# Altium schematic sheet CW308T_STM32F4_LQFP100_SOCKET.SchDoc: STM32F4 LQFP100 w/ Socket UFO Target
size Tabloid; DrawnBy: Joe Grand; Organization: Grand Idea Studio, Inc.; Revision: A; SheetNumber: 1; SheetTotal: 1; SheetApproved: YES
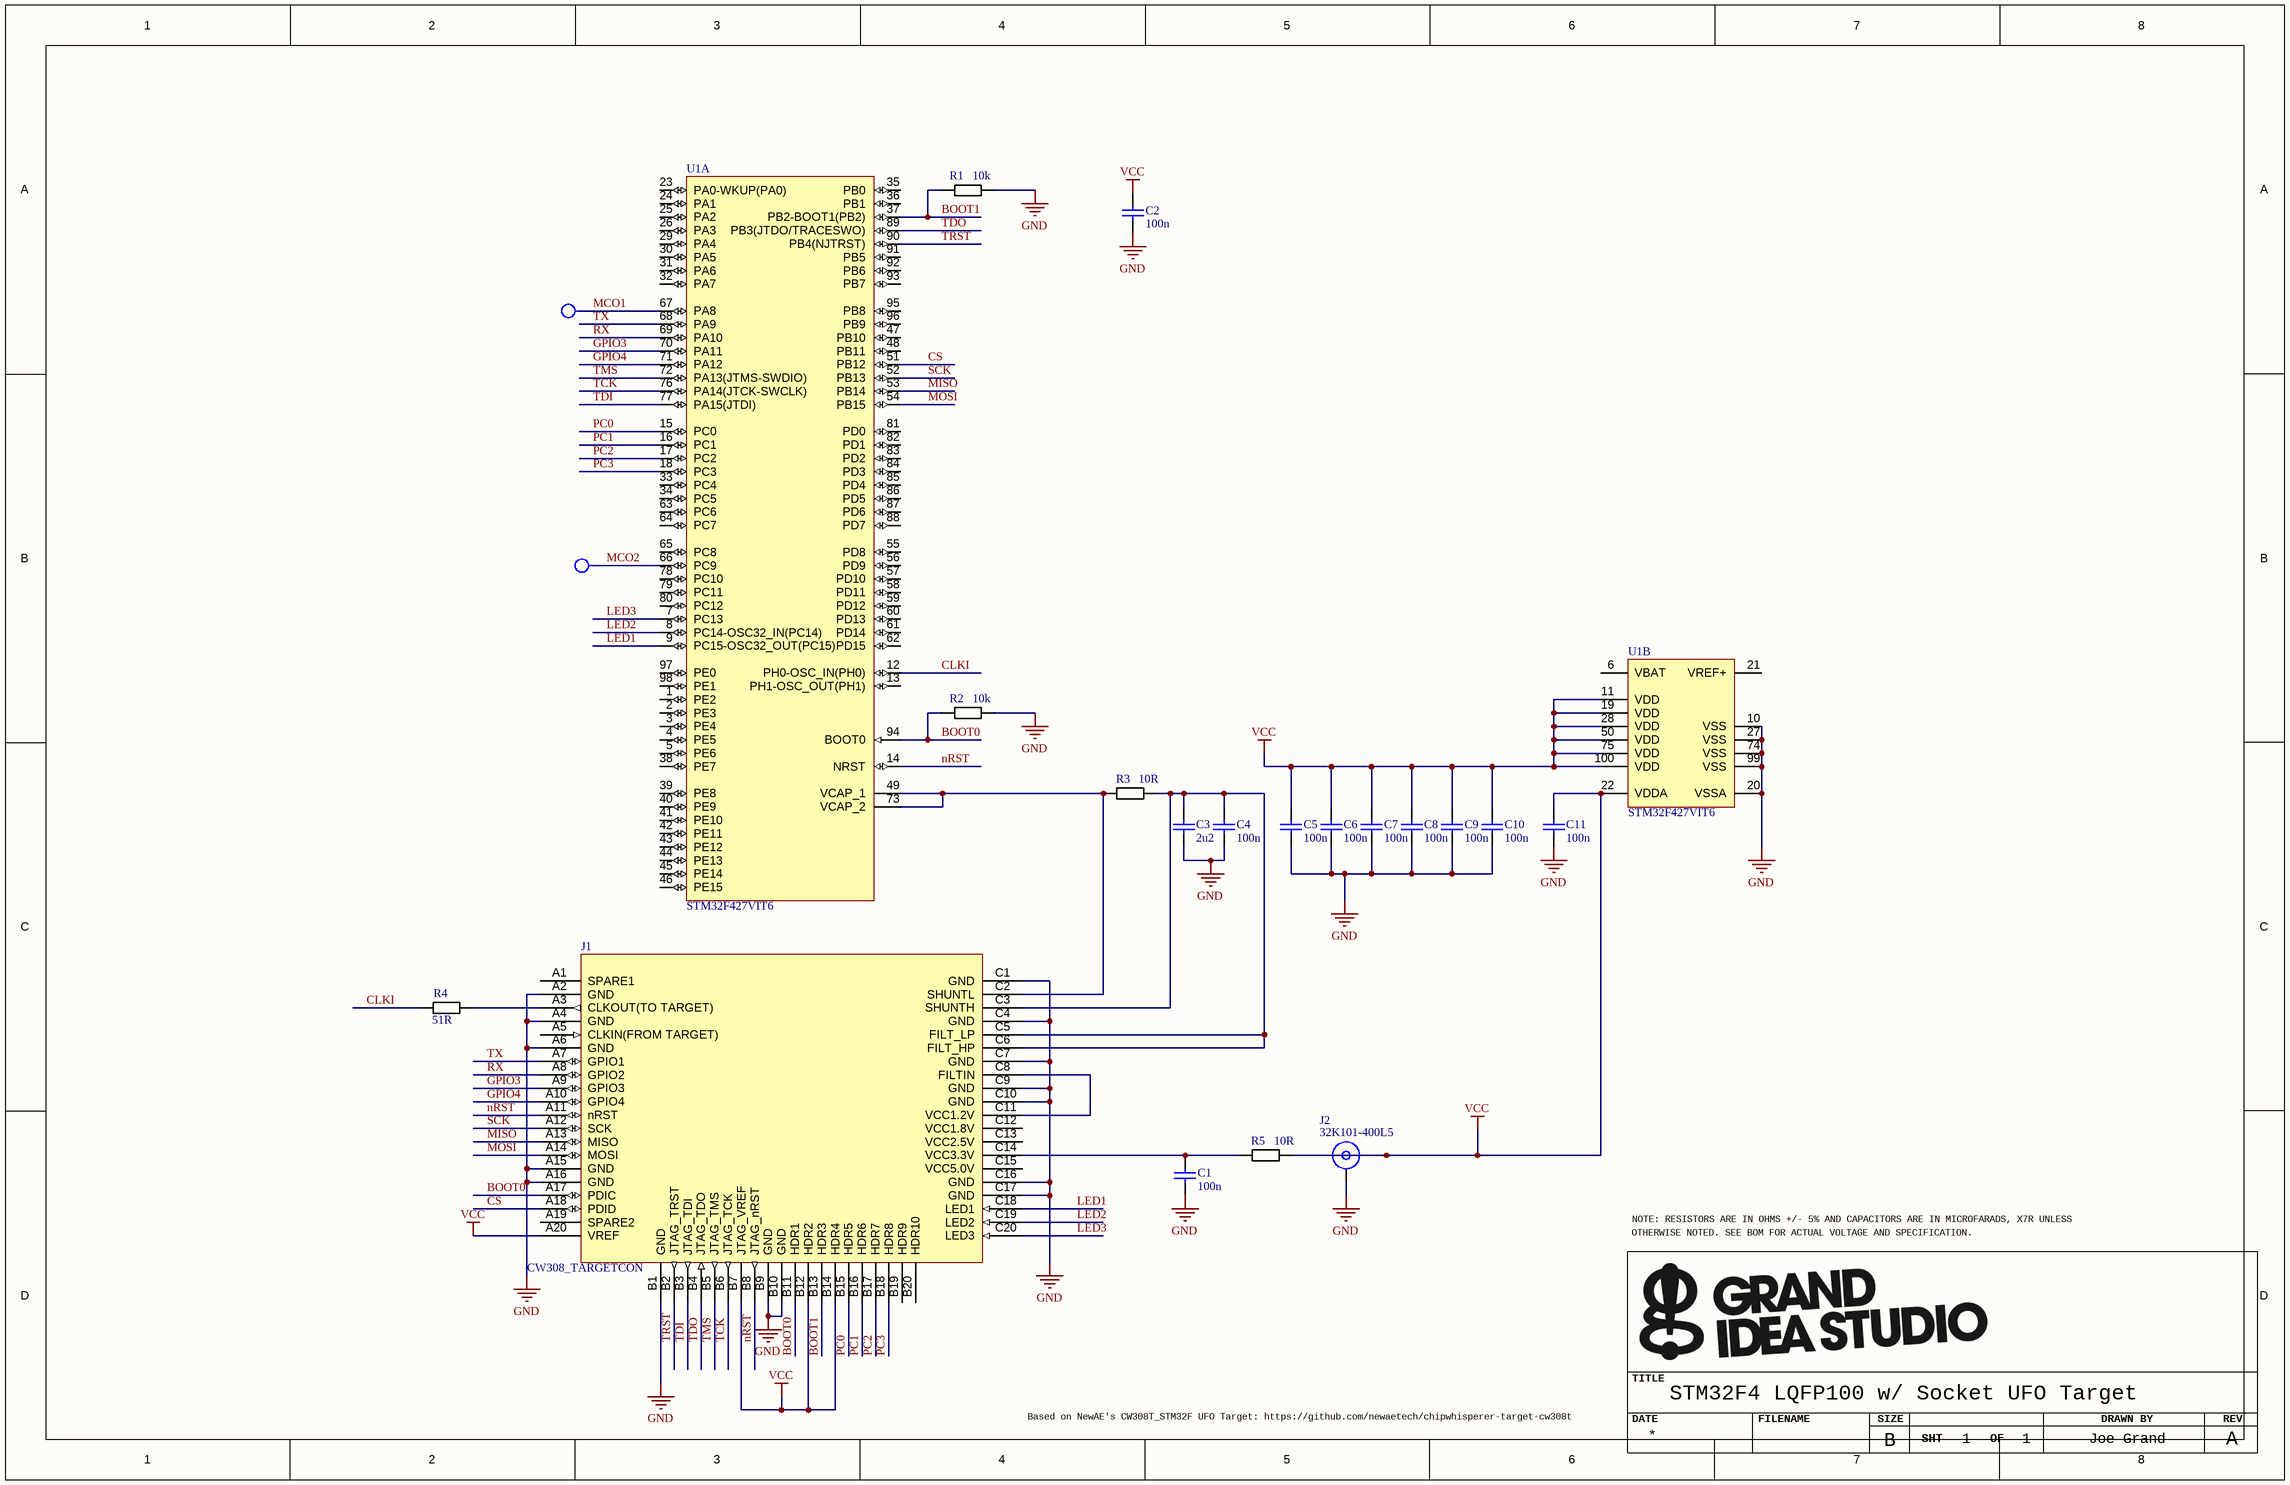
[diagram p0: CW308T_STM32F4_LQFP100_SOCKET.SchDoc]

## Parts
*  Page Size: B  RevCode: A  Page Count: 1  OrgName: Joe Grand  Title: STM32F4 LQFP100 w/ Socket UFO Target  (hidden comment: GIS Title Block)  (graphical)
C1  100n  [CAPC0603_M]
C2  100n  [CAPC0603_M]
C3  2u2  [CAPC0603_M]
C4  100n  [CAPC0603_M]
C5  100n  [CAPC0603_M]
C6  100n  [CAPC0603_M]
C7  100n  [CAPC0603_M]
C8  100n  [CAPC0603_M]
C9  100n  [CAPC0603_M]
C10  100n  [CAPC0603_M]
C11  100n  [CAPC0603_M]
J1  CW308_TARGETCON  [CW308_TBOARD_CONN]
J2  32K101-400L5  [32K101-400L5]
R1  10k  [RESC1608X55N]
R2  10k  [RESC1608X55N]
R3  10R  [RESC1608X55N]
R4  51R  [RESC1608X55N]
R5  10R  [RESC1608X55N]
TP1  TESTPOINT  [TESTPOINT]  (value not drawn)
TP2  TESTPOINT  [TESTPOINT]  (value not drawn)
U1  STM32F427VIT6  [ALLSOCKET-QFP100]  (parts A,B of 2)

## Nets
GND: C1.2 C2.2 C3.2 C4.2 C5.2 C6.2 C7.2 C8.2 C9.2 C10.2 C11.2 J1.A2(GND) J1.A4(GND) J1.A6(GND) J1.A15(GND) J1.A16(GND) J1.B1(GND) J1.B9(GND) J1.B10(GND) J1.C1(GND) J1.C4(GND) J1.C7(GND) J1.C9(GND) J1.C10(GND) J1.C16(GND) J1.C17(GND) J2.MP R1.2 R2.2 U1.10(VSS) U1.20(VSSA) U1.27(VSS) U1.74(VSS) U1.99(VSS)
VCC: C2.1 C5.1 C6.1 C7.1 C8.1 C9.1 C10.1 C11.1 J1.A20(VREF) J1.B7(JTAG_VREF) J1.B12(HDR2) J1.B14(HDR4) J2.1 R5.2 U1.11(VDD) U1.19(VDD) U1.22(VDDA) U1.28(VDD) U1.50(VDD) U1.75(VDD) U1.100(VDD)
BOOT0: J1.A17(PDIC) J1.B11(HDR1) R2.1 U1.94(BOOT0)
BOOT1: J1.B13(HDR3) R1.1 U1.37(PB2-BOOT1(PB2))
CLKI: R4.1 U1.12(PH0-OSC_IN(PH0))
CS: J1.A18(PDID) U1.51(PB12)
GPIO3: J1.A9(GPIO3) U1.70(PA11)
GPIO4: J1.A10(GPIO4) U1.71(PA12)
LED1: J1.C18(LED1) U1.9(PC15-OSC32_OUT(PC15))
LED2: J1.C19(LED2) U1.8(PC14-OSC32_IN(PC14))
LED3: J1.C20(LED3) U1.7(PC13)
MCO1: TP1.1 U1.67(PA8)
MCO2: TP2.1 U1.66(PC9)
MISO: J1.A13(MISO) U1.53(PB14)
MOSI: J1.A14(MOSI) U1.54(PB15)
nRST: J1.A11(nRST) J1.B8(JTAG_nRST) U1.14(NRST)
PC0: J1.B15(HDR5) U1.15(PC0)
PC1: J1.B16(HDR6) U1.16(PC1)
PC2: J1.B17(HDR7) U1.17(PC2)
PC3: J1.B18(HDR8) U1.18(PC3)
RX: J1.A8(GPIO2) U1.69(PA10)
SCK: J1.A12(SCK) U1.52(PB13)
TCK: J1.B6(JTAG_TCK) U1.76(PA14(JTCK-SWCLK))
TDI: J1.B3(JTAG_TDI) U1.77(PA15(JTDI))
TDO: J1.B4(JTAG_TDO) U1.89(PB3(JTDO/TRACESWO))
TMS: J1.B5(JTAG_TMS) U1.72(PA13(JTMS-SWDIO))
TRST: J1.B2(JTAG_TRST) U1.90(PB4(NJTRST))
TX: J1.A7(GPIO1) U1.68(PA9)
NetC1_1: C1.1 J1.C14(VCC3.3V) R5.1
NetC3_1: C3.1 C4.1 J1.C3(SHUNTH) J1.C5(FILT_LP) J1.C6(FILT_HP) R3.2
NetJ1_A3: J1.A3(CLKOUT(TO_TARGET)) R4.2
NetJ1_C2: J1.C2(SHUNTL) R3.1 U1.49(VCAP_1) U1.73(VCAP_2)
NetJ1_C8: J1.C8(FILTIN) J1.C11(VCC1.2V)

Not connected (* = marked no-connect by the designer): J1 A1(SPARE1) A5(CLKIN(FROM_TARGET)) A19(SPARE2) B19(HDR9) B20(HDR10) C12(VCC1.8V) C13(VCC2.5V) C15(VCC5.0V); U1 1(PE2) 2(PE3) 3(PE4) 4(PE5) 5(PE6) 6(VBAT) 13(PH1-OSC_OUT(PH1)) 21(VREF+) 23(PA0-WKUP(PA0)) 24(PA1) 25(PA2) 26(PA3) 29(PA4) 30(PA5) 31(PA6) 32(PA7) 33(PC4) 34(PC5) 35(PB0) 36(PB1) 38(PE7) 39(PE8) 40(PE9) 41(PE10) 42(PE11) 43(PE12) 44(PE13) 45(PE14) 46(PE15) 47(PB10) 48(PB11) 55(PD8) 56(PD9) 57(PD10) 58(PD11) 59(PD12) 60(PD13) 61(PD14) 62(PD15) 63(PC6) 64(PC7) 65(PC8) 78(PC10) 79(PC11) 80(PC12) 81(PD0) 82(PD1) 83(PD2) 84(PD3) 85(PD4) 86(PD5) 87(PD6) 88(PD7) 91(PB5) 92(PB6) 93(PB7) 95(PB8) 96(PB9) 97(PE0) 98(PE1)

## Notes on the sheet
- (near *) OTHERWISE NOTED. SEE BOM FOR ACTUAL VOLTAGE AND SPECIFICATION.
- (near *) NOTE: RESISTORS ARE IN OHMS +/- 5% AND CAPACITORS ARE IN MICROFARADS, X7R UNLESS
- Based on NewAE's CW308T_STM32F UFO Target: https://github.com/newaetech/chipwhisperer-target-cw308t

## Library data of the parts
C1 C2 C4-C11 = CCHIP-100n-0603: 100n, 0603; Component Group: Capacitor; Case-EIA: 0603; Case-Metric: 1608
C3 = CCHIP-2u2-0603: 2u2, 0603; Component Group: Capacitor; Case-EIA: 0603; Case-Metric: 1608
J1 = CW308_TBOARD: CW308 "Standard" Target Board Connector; Component Group: Mechanical; Pitch: 2.54mm
J2 = 32K145-400L5: SMA Right Angle Jack, Edge Mount, Up to 18 GHz, -55 to 155 degC; Design Note 1: Footprint in library is a generic example - only application specific footprint delivers High Performance; Desgin Note 2: For more information about DRC setting, please look at following webpage, http://techdocs.altium.com/display/SCRT/Design+Rule+for+Edge-Mount+Connectors
R1 R2 = RCHIP-10K-0603: 10k res, 0603, 1%, 1/10W; Manufacture 1: Yageo; Manufacture Part Number 1: RC0603FR-0710KL; Component Group: Resistor; Case-EIA: 0603; Case-Metric: 1608; Rated Power: 0.1W; Rated Voltage: 75VDC
R3 R5 = RCHIP-10R-0603: 10R res, 0603, 1%, 1/10W; Manufacture 1: Yageo; Manufacture Part Number 1: RC0603FR-0710RL; Component Group: Resistor; Case-EIA: 0603; Case-Metric: 1608; Rated Power: 0.1W; Rated Voltage: 75VDC
R4 = RCHIP-100R-0603: 100R res, 0603, 1%, 1/10W; Manufacture 1: Yageo; Manufacture Part Number 1: RC0603FR-07100RL; Component Group: Resistor; Case-EIA: 0603; Case-Metric: 1608; Rated Power: 0.1W; Rated Voltage: 75VDC
U1 = STM32F427VIT6: ARM Cortex-M4 32-bit MCU+FPU, 210 DMIPS, 2048 kB Flash, 256 kB Internal RAM, 82 I/Os, 100-pin LQFP, -40 to 85 degC, Tray; Manufacturer: STMicroelectronics; D/A Converter: 2x12-bit; FLASH Size (Prog) (kB): 2048; I/Os (High Current): 82; Internal RAM Size (kB): 256; Operating Frequency(F) (Processor speed) (MHz): 168; Supply Voltage(Vcc) max (V): 3.6; Supply Voltage(Vcc) min (V): 1.8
